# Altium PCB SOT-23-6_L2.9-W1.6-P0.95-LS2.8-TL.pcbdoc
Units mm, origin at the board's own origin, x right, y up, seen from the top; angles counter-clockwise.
Board outline 16.17 x 16.06 mm, 2 copper layers (Top Layer, Bottom Layer), stack 0 mm thick; 1 components, 0 nets, 6 pads, 0 vias.
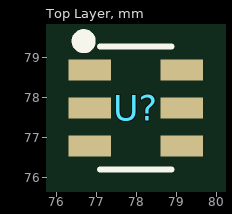
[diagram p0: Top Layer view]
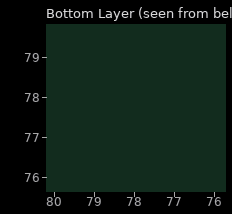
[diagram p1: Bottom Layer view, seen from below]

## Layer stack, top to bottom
Top Layer: signal copper (thickness not stored)
Bottom Layer: signal copper (thickness not stored)

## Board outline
86.015,69.85 69.85,69.85 69.85,85.907 86.015,85.907

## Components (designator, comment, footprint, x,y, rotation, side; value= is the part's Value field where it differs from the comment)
U? "" SOT-23-6_L2.9-W1.6-P0.95-LS2.8-TL 77.98,77.739 r0 top

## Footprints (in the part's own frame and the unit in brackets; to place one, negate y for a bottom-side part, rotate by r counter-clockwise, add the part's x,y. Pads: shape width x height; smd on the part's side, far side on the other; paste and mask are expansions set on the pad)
SOT-23-6_L2.9-W1.6-P0.95-LS2.8-TL [mm]
  rect 1.072x0.532 smd: 1(-1.149,0.95) 2(-1.149,0) 3(-1.149,-0.95) 4(1.149,-0.95) 5(1.149,0) 6(1.149,0.95)
  silkscreen extent -1.45,-1.54 0.89,1.82

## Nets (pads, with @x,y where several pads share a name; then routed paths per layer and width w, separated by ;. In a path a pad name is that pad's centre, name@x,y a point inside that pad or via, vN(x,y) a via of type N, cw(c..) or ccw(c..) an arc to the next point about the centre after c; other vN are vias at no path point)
pads on no net: U?.1 U?.2 U?.3 U?.4 U?.5 U?.6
